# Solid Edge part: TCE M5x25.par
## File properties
Title: 1320300093
Subject: Vite TCEI M5x25
Author: g_deluca
Template: RBuno.par
Last saved by: g_deluca
Revision: 20
Application: Solid Edge
Material: Classe 8.8
Tipo di contenuto documento: 0
Company: EFFEBI S.p.A.
Codice: Codice
Indice rev.: Rev.
Data rev.: Data rev.
Firma rev.: Firma rev.
Descrizione rev.: Descrizione rev.
Densità: 7860.000 kg/m^3
Precisione: 0.99
Document Number: UNI 5931
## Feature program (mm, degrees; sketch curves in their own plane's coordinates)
sketch for "unnamed Protrusion 1" plane through (0, 0, 0) normal (0, 0, 1) x-axis (1, 0, 0)
extrude "unnamed Protrusion 1" add finite 5 along +normal
sketch for "ExtrudedCutout_1" plane through (0, 0, 5) normal (0, 0, 1) x-axis (-1, 0, 0)
  line (2, 1.1547) -> (2, -1.1547)
  line (0, -2.3094) -> (2, -1.1547)
  line (-2, -1.1547) -> (0, -2.3094)
  line (-2, 1.1547) -> (-2, -1.1547)
  line (-2, 1.1547) -> (0, 2.3094)
  line (0, 2.3094) -> (2, 1.1547)
extrude "ExtrudedCutout_1" cut finite 3 along -normal
sketch for "ExtrudedProtrusion_4" plane through (0, 0, 0) normal (0, 0, -1) x-axis (0, -1, 0)
extrude "ExtrudedProtrusion_4" add finite 25 along +normal
thread "unnamed Thread 1"
fillet "Rotondo_2" radius 0.5
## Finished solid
Body 1: solid body, 19 faces, 35 edges, 18 vertices.
  Faces by surface: plane 10, cylinder 8, torus 1
  Edges by curve: line 24, ellipse 6, circle 5
Bounding box of the edges (mm; curved faces can reach further): 8.500 x 8.500 x 30.000, from (-4.25, -4.25, -25) to (4.25, 4.25, 5).
Cylindrical faces by radius (mm): R0.5 x6, R2.5 x1, R4.25 x1
Toroidal faces (ring radius, tube radius in mm): R3.75 r0.5 x1
Planar faces by outward normal: +x 1, +z 2, -x 1, -z 2, oblique 4
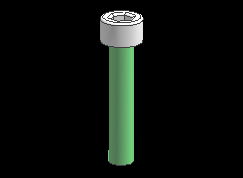
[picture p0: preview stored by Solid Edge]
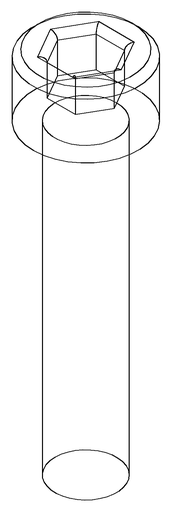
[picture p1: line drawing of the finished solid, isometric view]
